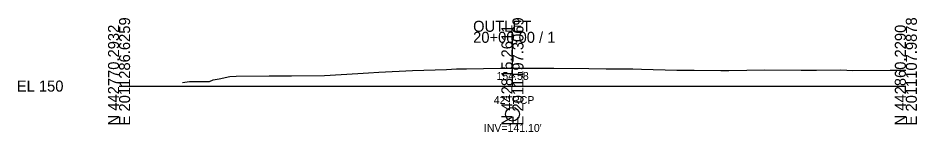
# Model space of a CAD drawing. Extents: x -26 to 1203, y -15 to 9526.
# Drawn here: x 974.3 to 1202.8, y -11.7 to 17.3 of the extents above; entities that cross this region are included whole.
import ezdxf

# ---------------------------------------------------------------- set-up
doc = ezdxf.new("R2010")
doc.units = 0
for name, color, linetype in [('Exist Cross Section Cell', 7, 'Continuous'), ('Exist XS Center Line Elevation Label', 7, 'Continuous'), ('Exist XS Ground Line', 7, 'Continuous'), ('Prop XSC Text', 7, 'Continuous')]:
    doc.layers.add(name, color=color, linetype=linetype)

msp = doc.modelspace()

# ---------------------------------------------------------------- linework, layer by layer
at = {"layer": 'Exist Cross Section Cell'}
for p, q in [((1100, 0), (1100, 13.81)), ((1000, 0), (1100, 0)), ((1100, 0), (1200, 0))]:
    msp.add_line(p, q, dxfattribs=at)
at = {"layer": 'Exist XS Ground Line'}
msp.add_lwpolyline([(1016.11, 0.92), (1017.91, 1.17), (1022.95, 1.13), (1023.92, 1.61), (1025.43, 1.86), (1028.16, 2.43), (1029.81, 2.49), (1038.15, 2.58), (1041.01, 2.61), (1043.82, 2.6), (1052.2, 2.68), (1060.7, 3.21), (1063.4, 3.35), (1066.06, 3.51), (1074.59, 3.94), (1083.24, 4.26), (1085.79, 4.37), (1088.3, 4.42), (1096.98, 4.6), (1100, 4.58), (1105.79, 4.53), (1108.18, 4.53), (1110.54, 4.52), (1119.38, 4.47), (1123.86, 4.43), (1130.57, 4.36), (1132.78, 4.29), (1141.77, 4.07), (1146.2, 4.06), (1152.96, 3.99), (1153.65, 3.99), (1155.01, 3.99), (1164.16, 4.1), (1173.43, 4.05), (1175.36, 4.06), (1177.25, 4.07), (1183.44, 4.13), (1186.55, 3.99), (1195.98, 4.08), (1197.75, 4.05), (1199.49, 4.07), (1200, 4.08)], dxfattribs=at)
at = {"layer": 'Prop XSC Text'}
msp.add_circle((1100, -7.15), 1.75, dxfattribs=at)

# ---------------------------------------------------------------- texts
at = {"layer": 'Exist Cross Section Cell'}
for s, p in [('E 2011286.6259', (1002.8, -10)), ('E 2011197.3069', (1102.8, -10)), ('E 2011107.9878', (1202.8, -10)), ('N 442770.2932', (1000, -10)), ('N 442815.2611', (1100, -10)), ('N 442860.2290', (1200, -10))]:
    msp.add_text(s, height=2.8, rotation=90, dxfattribs=at).set_placement(p)
for s, p in [('OUTLET', (1090, 13.81)), ('20+00.00 / 1', (1090, 11.01)), ('EL 150', (974, -1.4))]:
    msp.add_text(s, height=2.8, dxfattribs=at).set_placement(p)
at = {"layer": 'Exist XS Center Line Elevation Label'}
msp.add_text('154.58', height=2, dxfattribs=at).set_placement((1095.96, 1.58))
at = {"layer": 'Prop XSC Text'}
for s, p in [('42" RCP', (1095.26, -4.54)), ("INV=141.10'", (1092.73, -11.64))]:
    msp.add_text(s, height=2, dxfattribs=at).set_placement(p)

doc.saveas('drawing.dxf')
